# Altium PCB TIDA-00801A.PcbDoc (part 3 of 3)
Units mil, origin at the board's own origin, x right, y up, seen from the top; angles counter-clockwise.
Board outline 5000 x 3000 mil, 6 copper layers (Top Layer, Signal Layer 1, Signal Layer 2, Signal Layer 3, Signal Layer 4, Bottom Layer), stack 60.502 mil thick; 195 components, 95 nets, 602 pads, 757 vias.
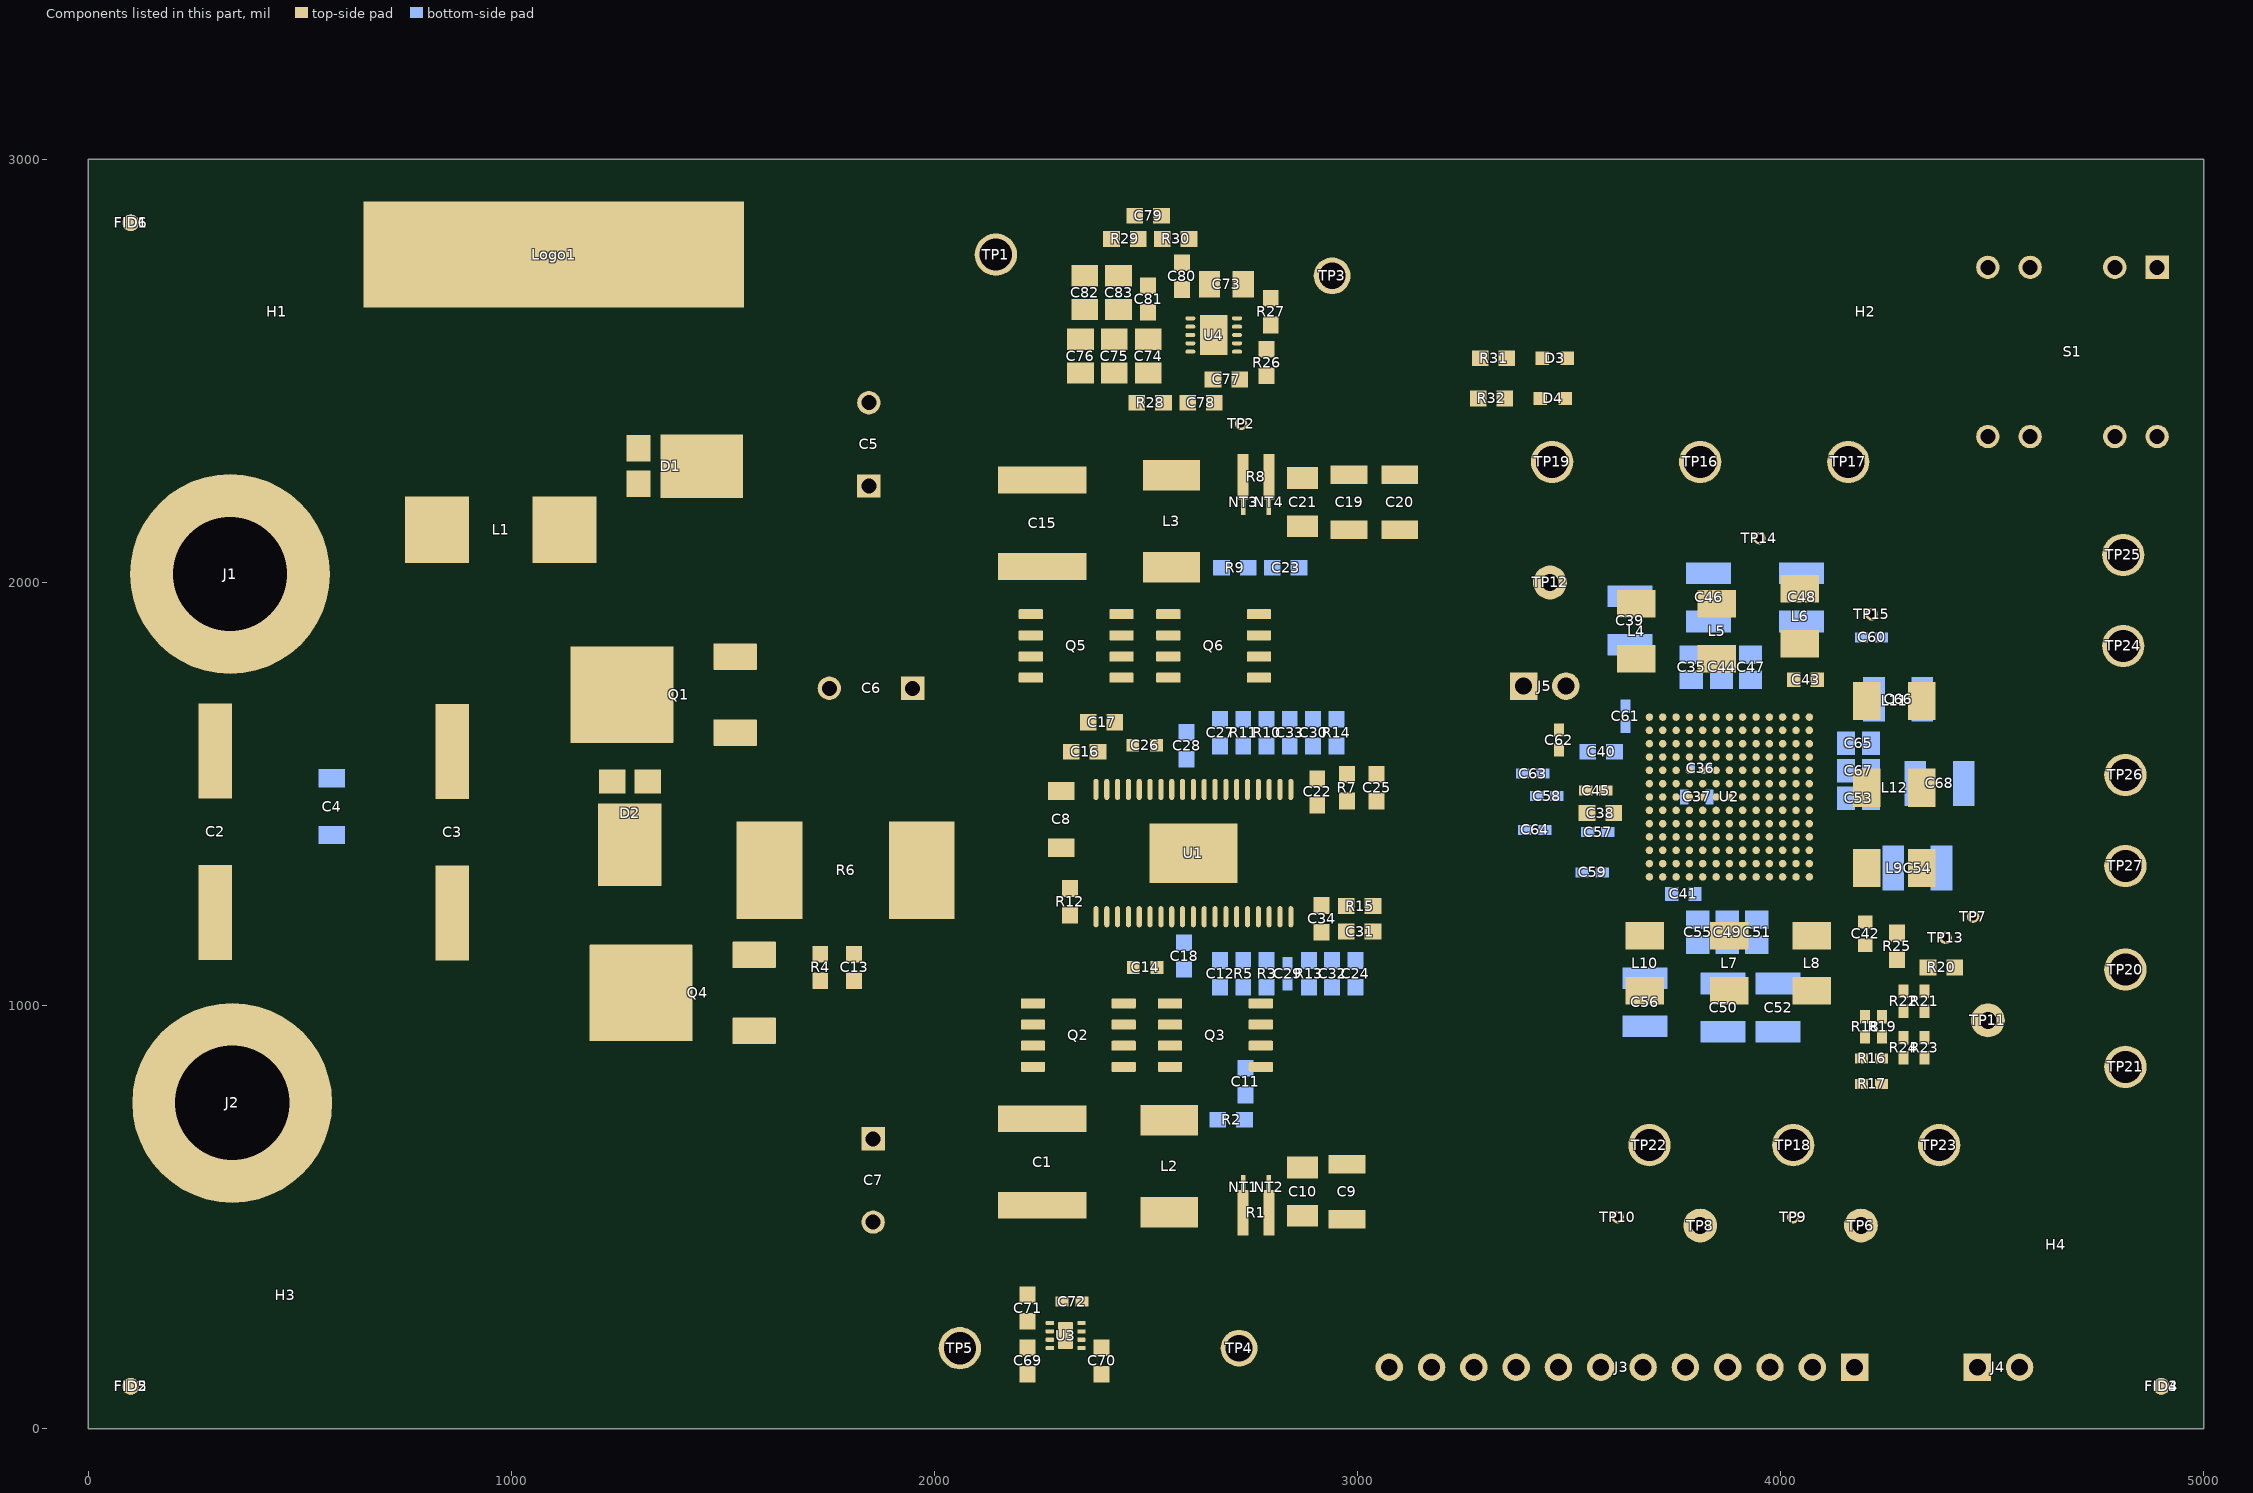
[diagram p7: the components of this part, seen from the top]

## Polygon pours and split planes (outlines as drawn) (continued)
NetL10_1 on Top Layer "TOP-SMPS7_SW" (solid, pour order 214): 3765.43,1308.21 3765.43,1331.31 3765.59,1331.85 3765.86,1332.95 3766.04,1334.08 3766.11,1335.22 3766.09,1336.36 3765.96,1337.5 3765.74,1338.62 3765.59,1339.17 3765.43,1339.71 3765.43,1362.81 3765.59,1363.35 3765.86,1364.45 3766.04,1365.58 3766.11,1366.72 3766.09,1367.86 3765.96,1369 3765.74,1370.12 3765.59,1370.67 3765.43,1371.21 3765.43,1377.83 3800.43,1377.83 3800.43,1149.83 3780.61,1130 3635.43,1130 3635.43,1157.83 3635.43,1199.88 3665.12,1199.88 3765.43,1299.81 3765.59,1300.35 3765.86,1301.45 3766.04,1302.58 3766.11,1303.72 3766.09,1304.86 3765.96,1306 3765.74,1307.12 3765.59,1307.67
NetL9_1 on Top Layer "TOP-SMPS6_SW" (solid, pour order 210): 4025.43,1447.83 4150.43,1447.83 4240.43,1357.83 4240.43,1287.83 4235.43,1282.83 4170.43,1282.83 4075.43,1417.83 4025.43,1417.83 4025.43,1447.83
NetL8_1 on Top Layer "TOP-SMPS5_SW" (solid, pour order 213): 3989.43,1231.94 4025.43,1197.83 4120.43,1197.83 4120.43,1132.83 4005.04,1132.83 4003.97,1133.67 4003,1134.37 4001.96,1134.98 4000.88,1135.51 3999.75,1135.93 3998.59,1136.26 3997.41,1136.48 3996.21,1136.6 3995.01,1136.62 3993.81,1136.53 3992.62,1136.34 3991.45,1136.04 3990.32,1135.64 3989.22,1135.15 3988.17,1134.56 3987.17,1133.88 3986.89,1133.67 3985.82,1132.83 3955.43,1132.83 3940.43,1147.83 3940.43,1205.05 3900.43,1262.83 3900.43,1377.83 3928.43,1377.83 3928.43,1298.83 3939.43,1287.83 3965.43,1287.83 3989.43,1263.83 3989.43,1231.94
NetL7_1 on Top Layer "TOP-SMPS4_SW" (solid, remove dead copper, pour order 207): 3920.43,1132.83 3820.43,1132.83 3820.43,1272.83 3829.72,1282.12 3856.25,1282.12 3865.43,1292.83 3865.43,1377.83 3890.43,1377.83 3890.43,1257.83 3920.43,1212.83 3920.43,1132.83
NetL6_1 on Top Layer "TOP-SMPS3_SW" (solid, pour order 211): 3915.43,1847.83 3965,1890 4090.43,1890 4090.43,1820.33 4005,1820.33 3963.17,1776.98 3962.22,1775.77 3961.57,1774.76 3961.01,1773.69 3960.6,1772.73 3960.27,1771.75 3959.98,1770.58 3959.79,1769.39 3959.71,1768.19 3959.73,1766.98 3959.85,1765.79 3960.08,1764.61 3960.27,1763.91 3960.43,1763.36 3960.43,1682.42 3960.43,1681.52 3960.43,1650.92 3960.43,1650.02 3960.43,1619.42 3960.43,1618.52 3960.43,1612.83 3955.43,1607.83 3930.43,1607.83 3930.43,1692.83 3915.43,1707.83
NetL5_1 on Top Layer "TOP-SMPS2_SW" (solid, pour order 208): 3835.43,1607.83 3835.43,1722.83 3800.43,1757.83 3800.43,1852.83 3900.43,1852.83 3900.43,1722.83 3865.43,1692.83 3865.43,1607.83 3835.43,1607.83
NetL4_1 on Top Layer "TOP-SMPS1_SW" (solid, pour order 209): 3786.65,1694.92 3694.11,1782.83 3600.43,1782.83 3600.43,1852.83 3695.43,1852.83 3825.43,1722.83 3825.43,1607.83 3800.43,1607.83 3800.43,1681.83 3797.34,1684.77 3797.04,1685.76 3796.66,1686.83 3796.19,1687.87 3795.64,1688.87 3794.99,1689.81 3794.27,1690.69 3793.47,1691.51 3792.6,1692.25 3791.68,1692.92 3790.7,1693.5 3789.67,1693.99 3788.6,1694.39 3787.66,1694.67 3786.65,1694.92
3V3 on Top Layer "TOP-V_LDOUSB_IN2 2" (solid, pour order 201): 4002.96,1795.24 4020.43,1810 4055,1810 4055,1760 4020.43,1727.83 4020.43,1647.83 4015.43,1642.83 3995.43,1642.83 3987.28,1650.98 3987.28,1767.17 3987.29,1768.37 3987.28,1779.67 3998.69,1791.09 4000,1792.01 4000.91,1792.8 4001.75,1793.66 4002.51,1794.59
3V3 on Top Layer "TOP-V_LDOUSB_IN2 1" (solid, pour order 203): 4026.43,1395.83 4026.43,1407.83 4070.43,1407.83 4080.43,1397.83 4080.43,1389.5 4188.85,1217.83 4230.43,1217.83 4230.43,1187.83 4160.43,1187.83 4085.43,1292.83 4085.43,1337.83 4070.43,1352.83 4065.43,1352.83 4050.43,1367.83 4050.43,1371.83 4026.43,1395.83
5V0 on Top Layer "TOP-V_LDOUSB_IN2" (solid, pour order 198): 3692.82,1575.22 3700.43,1550 3660,1550 3625.43,1582.83 3625.43,1627.83 3645.43,1627.83 3685.43,1597.83 3700.43,1597.83 3700.43,1584.22 3698.58,1583.06 3697.64,1582.41 3696.76,1581.68 3695.95,1580.88 3695.21,1580.01 3694.55,1579.08 3693.97,1578.1 3693.48,1577.07 3693.12,1576.11
LDOVRTC on Top Layer "TOP-LDORTC" (solid, pour order 193): 3457.5,1619.96 3457.5,1569.96 3492.5,1569.96 3492.5,1619.96 3457.5,1619.96
3V3 on Top Layer "TOP-VSYS 6" (solid, pour order 194): 4076.43,1515.83 4027.43,1515.83 4027.43,1564.83 4076.43,1564.83 4076.43,1515.83
3V3 on Top Layer "TOP-VSYS 5" (solid, pour order 200): 3920.43,1607.83 3870.43,1607.83 3870.43,1687.83 3875.43,1692.83 3920.43,1692.83 3920.43,1607.83
3V3 on Top Layer "TOP-VSYS 4" (solid, pour order 199): 3856.43,1294.83 3806.43,1294.83 3806.43,1377.83 3856.43,1377.83 3856.43,1294.83
3V3 on Top Layer "TOP-VSYS 3" (solid, pour order 189): 4027.43,1452.83 4027.43,1469.83 4076.43,1469.83 4076.43,1452.83 4027.43,1452.83
3V3 on Top Layer "TOP-VSYS 2" (solid, pour order 190): 3784.84,1690.83 3793.43,1682.67 3793.43,1614.83 3788.43,1609.83 3780.43,1609.83 3775.43,1614.83 3775.43,1684.83 3780.43,1690.83 3784.84,1690.83
3V3 on Top Layer "TOP-VSYS 1" (solid, pour order 191): 3950.43,1300.83 3946.43,1295.83 3938.43,1295.83 3932.65,1300.65 3932.65,1375.83 3950.43,1375.83 3950.43,1300.83
5V0 on Top Layer "TOP-LDO12_IN 1" (solid, pour order 197): 3700.43,1447.83 3660.43,1447.83 3630.43,1432.83 3590.43,1432.83 3590.43,1477.83 3690.43,1477.83 3694.15,1472.26 3694.3,1471.84 3694.75,1470.79 3695.3,1469.78 3695.92,1468.83 3696.63,1467.94 3697.42,1467.11 3697.54,1466.99 3697.86,1466.69 3700.43,1462.83 3700.43,1447.83
SMPS7 on Top Layer "TOP-N46924472" (solid, pour order 204): 3620.43,922.83 3620.43,972.83 3635.43,992.83 3635.43,1042.83 3720.43,1042.83 3720.43,992.83 3740.43,972.83 3740.43,922.83 3620.43,922.83
SMPS3 on Top Layer "TOP-N46921072" (solid, pour order 206): 4000,1950 4000,2020 3985,2040 3985,2090 4105,2090 4105,2040 4090,2020 4090,1950 4000,1950
SMPS3 on Top Layer "Top Layer-No Net" (solid, remove dead copper, pour order 195): 2510,2655 2560,2655 2595,2620 2600,2615 2610,2615 2615,2610 2615,2600 2590,2600 2575,2600 2570,2605 2555,2620 2510,2620
VTT on Top Layer "Top Layer-No Net" (solid, remove dead copper, pour order 196): 2510,2600 2560,2600 2565,2595 2570,2590 2585,2590 2615,2590 2615,2575 2595,2575 2580,2575 2570,2575 2545,2550 2510,2550
VIN on Top Layer "Top Layer-No Net" (solid, remove dead copper, pour order 215): 1420,2355 1905,2355 2095,2355 2095,2165 2260,2165 2360,2165 2360,1990 2335,1965 2335,1860 2335,1770 2265,1700 2247.5,1682.5 2247.5,1082.5 2295,1035 2360,970 2360,910 2360,645 2135,645 1800,645 1800,715 2065,980 2065,1435 1790,1710 1790,1790 1420,1790
NetC45_1 on Signal Layer 2 "LY6-VBG_TPS" (solid, pour order 218): 3725.46,1498.91 3725.42,1487.84 3713.1,1487.84 3712.28,1488.24 3711.24,1488.7 3710.15,1489.06 3709.05,1489.33 3707.92,1489.5 3706.78,1489.57 3705.64,1489.55 3704.5,1489.42 3703.39,1489.19 3702.29,1488.87 3701.23,1488.46 3700.76,1488.24 3699.94,1487.84 3686.19,1487.84 3685.5,1487.87 3684.82,1487.96 3684.15,1488.1 3683.5,1488.31 3682.86,1488.57 3682.25,1488.89 3681.68,1489.26 3681.13,1489.68 3680.62,1490.14 3680.16,1490.65 3679.74,1491.19 3679.37,1491.77 3679.06,1492.38 3678.79,1493.01 3678.59,1493.67 3678.44,1494.34 3678.39,1494.69 3678.19,1495.81 3677.9,1496.91 3677.51,1497.99 3677.03,1499.02 3676.46,1500.01 3675.81,1500.94 3675.07,1501.82 3674.27,1502.63 3673.4,1503.36 3672.46,1504.02 3671.47,1504.59 3670.44,1505.07 3669.37,1505.47 3668.27,1505.76 3667.14,1505.96 3666.01,1506.06 3664.87,1506.06 3663.73,1505.97 3662.61,1505.77 3661.5,1505.48 3660.43,1505.09 3659.4,1504.61 3658.41,1504.04 3657.47,1503.38 3656.6,1502.65 3655.79,1501.85 3655.05,1500.97 3654.4,1500.04 3653.83,1499.05 3653.34,1498.02 3652.95,1496.95 3652.65,1495.84 3652.45,1494.72 3652.45,1494.69 3652.33,1494.01 3652.16,1493.35 3651.92,1492.7 3651.63,1492.08 3651.29,1491.48 3650.9,1490.92 3650.46,1490.39 3649.97,1489.91 3649.45,1489.47 3648.88,1489.07 3648.29,1488.73 3647.67,1488.44 3647.02,1488.2 3646.36,1488.02 3645.68,1487.9 3645,1487.84 3644.65,1487.84 3595.42,1487.84 3583.72,1496.94 3583.72,1528.43 3587.66,1532.37 3627.71,1532.37 3628.56,1531.93 3628.56,1531.92 3629.65,1531.42 3630.78,1531.01 3631.95,1530.7 3633.13,1530.49 3634.33,1530.39 3635.54,1530.39 3636.73,1530.5 3637.92,1530.71 3639.08,1531.02 3640.21,1531.44 3641.26,1531.93 3642.11,1532.37 3642.78,1532.37 3646.72,1536.31 3717.58,1536.31 3725.46,1528.43 3725.46,1513.18 3725.34,1512.71 3725.11,1511.59 3724.97,1510.46 3724.94,1509.31 3725.01,1508.18 3725.17,1507.05 3725.34,1506.29 3725.46,1505.82 3725.46,1498.91
5V0 on Signal Layer 2 "Top Layer-No Net" (solid, remove dead copper, pour order 219): 3620,1650 3475,1650 3471,1650 3436,1615 3431,1610 3390,1610 3170,1610 3120,1560 3115,1555 3115,1500 3115,665 3037.5,587.5 3015,565 2920,470 2865,415 2865,385 3050,255 3390,595 3505,710 3505,1215 3650,1360 3650,1395 3650,1620
3V3 on Signal Layer 3 "Top Layer-No Net" (solid, remove dead copper, pour order 221): 2897.17,2850 4347.17,2850 4672.17,2850 4672.17,225 3522.17,225 3022.17,225 2972.17,175 2847.17,50 2472.17,50 2472.17,460 2937.17,925 2937.17,965 2937.17,2485 2697.17,2725 2697.17,2850
VIN on Signal Layer 3 "Top Layer-No Net" (solid, remove dead copper, pour order 220): 1420,2355 1890,2355 2095,2150 2175,2150 2225,2100 2275,2050 2275,1975 2275,1825 2275,1725 2247.5,1697.5 2247.5,1082.5 2295,1035 2325,1005 2325,925 2325,850 2125,650 1800,650 1800,715 2065,980 2065,1435 1900,1600 1420,1600 1420,1695
GND on Signal Layer 3 "Top Layer-No Net" (solid, remove dead copper, pour order 222): 50,2850 2680,2850 2680,2670 2875,2475 2900,2450 2900,2400 2900,905 2425,430 2425,50 50,50
GND on Signal Layer 1 "Top Layer-No Net" (solid, remove dead copper, pour order 217): 50,2950 4950,2950 4950,50 50,50
GND on Signal Layer 4 "Top Layer-No Net" (solid, remove dead copper, pour order 223): 50,2950 4950,2950 4950,50 50,50

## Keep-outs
Keep-Out Layer:
  lines w10: -5,0 ccw(c0,0) 0,-5 ; -5,0 ccw(c0,0) 0,-5 ; -5,0 -5,3000 ; -5,3000 cw(c0,3000) 0,3005 ; -5,3000 cw(c0,3000) 0,3005 ; 0,-5 5000,-5 ; 0,3005 5000,3005 ; 5000,-5 ccw(c5000,0) 5005,0 ; 5000,-5 ccw(c5000,0) 5005,0 ; 5000,3005 cw(c5000,3000) 5005,3000 ; 5000,3005 cw(c5000,3000) 5005,3000 ; 5005,0 5005,3000
  text ".Layer_Name" at 577,-858.49 h60

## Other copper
Top Layer:
  rectangle net SMPS3: 2275,2620 2330,2670
  region net NetQ4_3: 1690,1440 1460,1440 1460,1030 1690,1030
  rectangle net SMPS9: 4361.56,1535 4870,1630
  region net GND: 3455,1688.62 3455,1643.62 3495,1643.62 3495,1688.62
  region net SMPS9: 4870,1460 4870,1582 4296,1582 4296,1460
  region net SMPS4_5: 3927,781 3927,1069 3811,1069 3811,781
  region net SMPS4_5: 4125,784 4125,1066 4019,1066 4019,784
  region net SMPS4_5: 4125,615 4125,992 3812,992 3812,615
  region net SMPS1_2: 3894,1927 3894,2345 3585,2345 3585,1927
  region net SMPS3: 4215,2072.83 4215,2345 3985,2345 3985,2072.83
  region net SMPS7: 3740,615 3740,930 3620,930 3620,615
  rectangle net VBAT: 55,1485 910,2350
  rectangle net NetD1_1: 955,1495 1405,2150
  rectangle net NetD2_3: 1070,910 1440,1480
  rectangle net PHB: 2410,1760 2605,1895
  rectangle net PHB: 2485,1760 2655,2075
  rectangle net PHA: 2415,690 2645,970
  rectangle net PHA: 2514,950 2645,1020
  rectangle net NetL3_2: 2490,2195 2740,2305
  rectangle net NetL2_2: 2485,455 2745,565
  rectangle net 5V0: 2780,435 3055,565
  rectangle net 3V3: 2777.72,2195 3175,2316.93
  rectangle net GND: 2830,2060 3150,2160
  rectangle net GND: 2830,590 3050,690
  rectangle net GND: 2139.3,490 2395,590
  rectangle net GND: 2110,2175 2380,2355
  rectangle net VIN: 2190,1490 2380,1530
  rectangle net GND: 2720,840 2850,970
  rectangle net GND: 2814,960 2850,990
  rectangle net GND: 2715,1725 2845,1895
  rectangle net 3V3: 2705,2620 2755,2710
  rectangle net 3V3: 2700,2700 2805,2785
  rectangle net 3V3: 4160,1180 4240,1225
  rectangle net GND: 4180,1115 4240,1160
  rectangle net 5V0: 2340,245 2395,365
  rectangle net 3V3: 2345,170 2415,215
  rectangle net 3V3: 2410,170 2600,210
  rectangle net 3V3: 2435,115 2600,175
  rectangle net 3V3_SW: 2120,170 2275,215
  rectangle net 3V3_SW: 2060,145 2180,235
  rectangle net NetD1_1: 960,2100 1335,2355
  pour cut-out: 3665,1775 3665,1650 3705,1610 3705,1440 3680,1415 3670,1415 3655,1400 3655,1310 3681.48,1283.52 3742.97,1283.52 3742.97,1302.97 3760,1320 3760,1380 3955,1380 3955,1295 3990,1295 4005,1280 4080,1280 4080,1334.49 4020,1394.49 4020,1605 4046,1631 4080,1631 4080,1635 4095,1650 4095,1705 4025,1705 4025,1635 4008.98,1618.98 3968.98,1618.98 3950,1600 3765,1600 3765,1625 3763.99,1626.01 3763.99,1706.01 3695,1775
  region net SMPS6: 4300,1385 4630,1385 4870,1145 4870,1030 4715,1030 4473.15,1271.85 4300,1271.85
  region net SMPS8: 4300,1785 4500,1785 4640,1925 4870,1925 4870,1665 4300,1665
  pour cut-out: 1440,1025 1670,1025 1670,900 1510,900 1440,900
  text ".CopyrightYear" at 542,70 h60
  text "TI" at 818,70 h60
  text "©" at 425,66.48 h105
  text ".Layer_Name" at 577,-858.49 h60
Signal Layer 1:
  pour cut-out: 3738.18,1899.94 ccw(c3753.23,1899.94) 3753.23,1884.88 ccw(c3753.23,1899.94) 3768.29,1899.94 ccw(c3753.23,1899.94) 3753.23,1914.99 ccw(c3753.23,1899.94)
  pour cut-out: 3958.88,1616.77 ccw(c3973.94,1616.77) 3973.94,1601.71 ccw(c3973.94,1616.77) 3988.99,1616.77 ccw(c3973.94,1616.77) 3973.94,1631.82 ccw(c3973.94,1616.77)
  pour cut-out: 3738.18,1649.94 ccw(c3753.23,1649.94) 3753.23,1634.88 ccw(c3753.23,1649.94) 3768.29,1649.94 ccw(c3753.23,1649.94) 3753.23,1664.99 ccw(c3753.23,1649.94)
  pour cut-out: 3958.88,1366.77 ccw(c3973.94,1366.77) 3973.94,1351.71 ccw(c3973.94,1366.77) 3988.99,1366.77 ccw(c3973.94,1366.77) 3973.94,1381.82 ccw(c3973.94,1366.77)
  pour cut-out: 3958.88,1366.77 ccw(c3973.94,1366.77) 3973.94,1351.71 ccw(c3973.94,1366.77) 3988.99,1366.77 ccw(c3973.94,1366.77) 3973.94,1381.82 ccw(c3973.94,1366.77)
  text ".Layer_Name" at 577,-858.49 h60
Signal Layer 2:
  rectangle net 5V0: 2335,255 3050,415
  region net 5V0: 3065,270 2930,135 2675,135 2540,270
  text ".Layer_Name" at 577,-858.49 h60
Signal Layer 3:
  pour cut-out: 3674.36,1868.76 ccw(c3689.42,1868.76) 3689.42,1853.7 ccw(c3689.42,1868.76) 3704.47,1868.76 ccw(c3689.42,1868.76) 3689.42,1883.81 ccw(c3689.42,1868.76)
  text ".Layer_Name" at 577,-858.49 h60
Signal Layer 4:
  rectangle net SMPS3: 2274,2621 2330,2685
  pour cut-out: 3706.01,1618.23 ccw(c3721.06,1618.23) 3721.06,1603.18 ccw(c3721.06,1618.23) 3736.12,1618.23 ccw(c3721.06,1618.23) 3721.06,1633.29 ccw(c3721.06,1618.23)
  pour cut-out: 3958.88,1366.77 ccw(c3973.94,1366.77) 3973.94,1351.71 ccw(c3973.94,1366.77) 3988.99,1366.77 ccw(c3973.94,1366.77) 3973.94,1381.82 ccw(c3973.94,1366.77)
  text ".Layer_Name" at 577,-858.49 h60
Bottom Layer:
  rectangle net SMPS3: 2274,2621 2321,2666
  rectangle net 3V3: 4110.43,1620 4145,1640
  rectangle net VBAT: 70,1510 850,2320
  rectangle net GND: 4235,1850 4320,1910
  region net SMPS1_2: 3741,1942 3741,2345 3562,2345 3562,1942
  region net SMPS1_2: 3894,1993 3894,2345 3729,2345 3729,1993
  region net SMPS3: 4215,2100 4215,2345 3985,2345 3985,2100
  region net SMPS7: 3740.72,615 3740.72,975 3620,975 3620,615
  rectangle net SMPS4_5: 3810,615 4125,965
  rectangle net SMPS9: 4395,1460 4870,1630
  rectangle net LDO3: 3964.87,1626.33 3985,1645
  rectangle net GND: 3505,1581 3564,1619
  rectangle net GND: 3384,1483 3415,1507
  pour cut-out: 3973.76,1753.96 3977.56,1750.16 3972.15,1744.75 3972.16,1744.74 3971.91,1744.51 3971.63,1744.3 3971.34,1744.11 3971.04,1743.95 3970.72,1743.82 3970.39,1743.72 3970.06,1743.65 3969.72,1743.6 3969.37,1743.59 3969.03,1743.6 3968.69,1743.65 3968.35,1743.72 3968.03,1743.82 3967.71,1743.95 3967.4,1744.11 3967.11,1744.3 3966.84,1744.51 3966.59,1744.74 3966.36,1744.99 3966.15,1745.27 3965.96,1745.56 3965.8,1745.86 3965.67,1746.18 3965.57,1746.51 3965.49,1746.84 3965.45,1747.14 3965.45,1754.52 3969.83,1754.52 3970.28,1754.41 3970.28,1754.4 3971.47,1754.18 3972.33,1754.08
  region net SMPS8: 4300,1785 4400,1785 4540,1925 4870,1925 4870,1665 4300,1665
  region net SMPS6: 4350,1385 4630,1385 4870,1145 4870,1030 4715,1030 4473.15,1271.85 4350,1271.85
  pour cut-out: 3738.18,1649.94 ccw(c3753.23,1649.94) 3753.23,1634.88 ccw(c3753.23,1649.94) 3768.29,1649.94 ccw(c3753.23,1649.94) 3753.23,1664.99 ccw(c3753.23,1649.94)
  pour cut-out: 3958.88,1366.77 ccw(c3973.94,1366.77) 3973.94,1351.71 ccw(c3973.94,1366.77) 3988.99,1366.77 ccw(c3973.94,1366.77) 3973.94,1381.82 ccw(c3973.94,1366.77)
  text ".Layer_Name" at 577,-858.49 h60

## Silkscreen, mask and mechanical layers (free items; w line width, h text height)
Top Overlay:
  text ".PCB_Rev" at 1344,2541 h110
  text ".tiD" at 805,2540 h110
  text "LDOVRTC" at 3535,2515 h75
  text "RESET_OUT" at 3535,2415 h75
  text "SYNC" at 3350,1820 h75
  text "VBAT" at 535,1805 h75
  text "GND" at 565,910 h75
  text "I2C_SDA" at 4460,210 h75 r45
  text "I2C_SCL" at 4560,210 h75 r45
  text "LDOUSB" at 3075,205 h75 r45
  text "LDOVRTC" at 3175,205 h75 r45
  text "GND" at 3275,205 h75 r45
  text "LDOVANA" at 3375,205 h75 r45
  text "LDO2" at 3475,205 h75 r45
  text "GND" at 3575,205 h75 r45
  text "LDO9" at 3675,205 h75 r45
  text "LDO1" at 3775,205 h75 r45
  text "GND" at 3875,205 h75 r45
  text "LDOLN" at 3975,205 h75 r45
  text "GND" at 4075,205 h75 r45
  text "LDO3" at 4175,205 h75 r45
  text ".Layer_Name" at 577,-858.49 h60
Bottom Overlay:
  text ".Layer_Name" at 577,-858.49 h60
Top Paste:
  text ".Layer_Name" at 577,-858.49 h60
Bottom Paste:
  text ".Layer_Name" at 577,-858.49 h60
Top Solder:
  text ".Layer_Name" at 577,-858.49 h60
  text ".Layer_Name" at 577,-858.49 h60
Bottom Solder:
  text ".Layer_Name" at 577,-858.49 h60
Drill Guide:
  text ".Layer_Name" at 577,-858.49 h60
M1 Board Outline:
  the board outline again, w10
  text ".Layer_Name" at 577,-858.49 h60
M2 Board Dimensions:
  rectangle: 125,-400 500,-275
  rectangle: 0,-275 125,-150
  lines w7: 0,-275 1000,-275 ; 125,-400 125,-150 ; 250,-400 250,-150 ; 500,-400 500,-150 ; 750,-400 750,-150 ; 0,-400 0,-150 1000,-150 1000,-400 0,-400
  text ".Layer_Name" at 577,-858.49 h60
M3 3D STEP Top:
  text ".Layer_Name" at 577,-858.49 h60
M4 3D STEP Bottom:
  text ".Layer_Name" at 577,-858.49 h60
M5 Assembly Top:
  lines w10: -292,-930.17 6308,-930.17 ; -292,-726.83 6310,-726.83 ; -292,-523.5 -292,-1133.5 3713,-1133.5 6310,-1133.5 6310,-523.5 -291.5,-523.5 -291.5,-1133.5 1284,-1133.5 ; 2173,-1133.5 2173,-523.5 ; 3440,-726.83 3440,-523.5 ; 4280,-726.83 4280,-523.5 ; 4902,-1140 4902,-937.17
  text "COMPONENTS MARKED 'DNP' SHOULD NOT BE POPULATED." at 1153.5,-318.5 h60
  text "ASSEMBLY VARIANT:" at 1153,-434 h60
  text ".VariantName" at 2189,-434 h60
  text "PCB VIEWED FROM TOP SIDE" at -228.5,-655.67 h60
  text "BOARD #:" at 2248,-655.67 h60
  text ".PRJ_Number" at 2793.5,-655.67 h60
  text "REV:" at 3638,-655.67 h60
  text ".PCB_Rev" at 3929.5,-655.67 h60
  text "SVN REV:" at 4476,-655.67 h60
  text ".VersionControl_RevNumber" at 4982,-655.67 h60
  text "PLOT NAME =" at -228.5,-1064.34 h60
  text ".plot_File_Name" at 577,-1064.34 h60
  text "GENERATED    :" at 2250,-1064.34 h60
  text ".Print_Date" at 3119.5,-1064.34 h60
  text ".Print_Time" at 3848.5,-1064.34 h60
  text "TEXAS INSTRUMENTS" at 5113,-1064.34 h60
M6 Assembly Bottom:
  lines w10: -292.5,-727.33 6309.5,-727.33 ; -290.5,-930.67 6309.5,-930.67 ; 1115.5,-1140.5 1115.5,-937.67 ; 1737.5,-727.33 1737.5,-524 ; 2577.5,-727.33 2577.5,-524 ; 3844.5,-1134 3844.5,-524 ; 4733.5,-1134 6309,-1134 6309,-524 -292.5,-524 -292.5,-1134 2304.5,-1134 6309.5,-1134 6309.5,-524
  text "COMPONENTS MARKED 'DNP' SHOULD NOT BE POPULATED." at 6102,-318 h60
  text ".VariantName" at 5058,-434 h60
  text "ASSEMBLY VARIANT:" at 6097,-434 h60
  text ".VersionControl_RevNumber" at 1035.5,-656.17 h60
  text "SVN REV:" at 1541.5,-656.17 h60
  text ".PCB_Rev" at 2088,-656.17 h60
  text "REV:" at 2379.5,-656.17 h60
  text ".PRJ_Number" at 3224,-656.17 h60
  text "BOARD #:" at 3769.5,-656.17 h60
  text "PCB VIEWED FROM BOTTOM SIDE" at 6246,-656.17 h60
  text "TEXAS INSTRUMENTS" at 904.5,-1064.84 h60
  text ".Print_Time" at 2169,-1064.84 h60
  text ".Print_Date" at 2898,-1064.84 h60
  text "GENERATED    :" at 3767.5,-1064.84 h60
  text ".plot_File_Name" at 5440.5,-1064.84 h60
  text "PLOT NAME =" at 6246,-1064.84 h60
M9 Title Sheet:
  drawing of 57 lines, arcs and shapes, not listed
  text "1" at 739.84,8036.5 h70
  text "2" at 3235.5,8036.5 h70
  text "3" at 5724.84,8036.5 h70
  text "4" at 8231.51,8036.5 h70
  text "5" at 10730.5,8036.5 h70
  text "6" at 13235.5,8036.5 h70
  text "A" at -416.5,6893.5 h70
  text "A" at 14383.5,6893.5 h70
  text "B" at -416.5,4513.5 h70
  text "B" at 14383.5,4513.5 h70
  text "C" at -416.5,2138.5 h70
  text "C" at 14383.5,2138.5 h70
  text "PROJECT TITLE:" at 11343.5,277.5 h45
  text ".PRJ_Title" at 11393.5,144.17 h70
  text "DESIGNED FOR:" at 11343.5,-23.5 h45
  text ".PRJ_Customer" at 11393.5,-163.5 h70
  text "D" at -416.5,-231.5 h70
  text "D" at 14383.5,-231.5 h70
  text "FILE NAME:" at 11343.5,-323.5 h45
  text ".PCB_File_Name_No_Path" at 11393.5,-443.5 h70
  text "Texas Instruments (TI) and/or its licensors do not warrant the accuracy or completeness of this specification" at 6374,-605.34 h45
  text "ENGINEER:" at 11343.5,-613.5 h45
  text "LAYOUT BY:" at 12848.5,-613.5 h45
  text "or any information contained therein. TI and/or its licensors do not warrant that this design will meet" at 6329.01,-718 h45
  text ".PRJ_Engineer" at 11393.5,-768.49 h70
  text ".PCB_Layout" at 12899,-768.49 h70
  text "the specifications, will be suitable for your application or fit for any particular purpose, or will operate in" at 6329.01,-830.67 h45
  text ".Layer_Name" at 577,-858.49 h60
  text "ALTIUM DESIGNER VERSION:" at 12848.5,-923.5 h45
  text "an implementation. TI and/or its licensors do not warrant that the design is production worthy. You should" at 6329.01,-943.33 h45
  text "completely validate and test your design implementation to confirm the system functionality for your application." at 6374,-1056 h45
  text ".print_Scale" at 11393.5,-1056.83 h70
  text ".Application_BuildNumber" at 12899,-1056.83 h70
  text "1" at 739.84,-1263.5 h70
  text "2" at 3235.5,-1263.5 h70
  text "3" at 5724.84,-1263.5 h70
  text "4" at 8231.51,-1263.5 h70
  text "5" at 10730.5,-1263.5 h70
  text "6" at 13235.5,-1263.5 h70
M10 Fab Notes:
  drawing of 185 lines, arcs and shapes, not listed
  text "DESIGN INFORMATION" at 12381.02,5910 h60
  text "MIN. TRACK WIDTH:" at 11736.46,5730 h60
  text "4" at 12832.7,5730 h60
  text "MIL" at 12987.46,5730 h60
  text "MIN. CLEARANCE:" at 11736.46,5598 h60
  text "4" at 12772.7,5598 h60
  text "MIL" at 12987.46,5598 h60
  text "MIN. VIA PAD SIZE:" at 11736.46,5466 h60
  text "17" at 12802.71,5466 h60
  text "MIL" at 12987.46,5466 h60
  text "0.05mm (2MIL)" at 12431.46,5324.29 h60
  text "MINIMUM ANNULAR RING" at 11407.23,5320 h60
  text "EXTERNAL" at 13139.46,5320 h60
  text "PER" at 11607.23,5202 h60
  text "IPC-D-275 CLASS 2 LEVEL C" at 11827.23,5202 h60
  text "MIL, HOLES" at 13315.46,5089.71 h60
  text "+/-" at 12923,5089 h60
  text "+/-" at 13777,5089 h60
  text "REGISTRATION TOLERANCES:" at 11407.23,5084 h60
  text "METAL" at 12607,5084 h60
  text "5" at 13183.2,5084 h60
  text "3" at 14016.2,5084 h60
  text "MIL" at 14132.46,5084 h60
  text "MATERIAL:" at 11332.46,4874.54 h60
  text "FR-4 High Tg" at 12318.9,4734.21 h60
  text "FR-408" at 11753.46,4725.64 h60
  text "X" at 12165.46,4725.64 h60
  text "OTHER" at 13241.46,4725.64 h60
  text "62 MIL (1.6mm) +/-10%" at 12073.56,4562.92 h60
  text "THICKNESS:" at 11407.23,4558.64 h60
  text "X" at 11945.4,4558.64 h60
  text "OTHER" at 13358.46,4558.64 h60
  text "TOLERANCE:" at 11407.23,4400.64 h60
  text "X" at 12246.53,4400.64 h60
  text "ANSI IPC-6012 TYPE 3 CLASS 2" at 12433.48,4400.64 h60
  text "OTHER +/-" at 12433.46,4244.64 h60
  text "BOW & TWIST:" at 11407.23,4087.64 h60
  text "X" at 12246.53,4087.64 h60
  text "ANSI IPC-6012 TYPE 3 CLASS 2" at 12433.48,4087.64 h60
  text "OTHER +/-" at 12433.46,3929.13 h60
  text "DRILLING:" at 11332.46,3790.64 h60
  text "REFERENCE:" at 11407.23,3673.64 h60
  text "X" at 12055.46,3673.64 h60
  text "AS SHOWN" at 12242.46,3673.64 h60
  text "X" at 12956.46,3673.64 h60
  text "NC_DRILL FILES" at 13093.46,3673.64 h60
  text "PTH MIN COPPER THICKNESS:" at 11407.23,3515.64 h60
  text "X" at 12757.46,3515.64 h60
  text "1MIL" at 12894.46,3515.64 h60
  text "OTHER" at 13391.46,3515.64 h60
  text "BOARD FINISH:" at 11332.46,3356.64 h60
  text "SILKSCREEN:" at 11487.68,3238.64 h60
  text "X" at 12436.46,3238.64 h60
  text "TOP" at 12562.46,3238.64 h60
  text "X" at 12946.46,3238.64 h60
  text "BOTTOM" at 13073.46,3238.64 h60
  text "SILKSCREEN COLOR:" at 11487.68,3071.64 h60
  text "X" at 12435.42,3071.64 h60
  text "WHITE" at 12562.46,3071.64 h60
  text "OTHER" at 13073.46,3071.64 h60
  text "SOLDER RESIST COLOR:" at 11487.68,2901.64 h60
  text "X" at 12055.42,2742.44 h60
  text "GREEN" at 12182.46,2742.44 h60
  text "BLUE" at 12773.46,2742.44 h60
  text "OTHER" at 13311.46,2742.44 h60
  text "IMMERSION GOLD (ENIG)" at 12393.46,2553.92 h60
  text "ENEPIG" at 13731,2550.64 h60
  text "SURFACE FINISH:" at 11332.46,2549.64 h60
  text "X" at 12206.51,2549.64 h60
  text "IMM. TIN/SILVER OR EQUIV" at 11662,2392.64 h60
  text "OTHER" at 13093.46,2392.64 h60
  text "ARRAY/PANEL:" at 11332.46,2213.64 h60
  text "CUT AND TRIM PER MECH LAYER 1" at 12393.46,2209.35 h60
  text "N.C. ROUTE" at 12393.46,2057.64 h60
  text "X" at 13072.46,2057.64 h60
  text "V. SCORE" at 13259.46,2057.64 h60
  text "CERTIFICATION:" at 11332.46,1920.64 h60
  text "MATERIALS AND WORKMANSHIP FOR ALL PCBS" at 12057.46,1920.64 h60
  text "TO MEET OR EXCEED THE REQUIREMENTS OF:" at 12057.46,1822.64 h60
  text "X" at 11683.96,1686.13 h60
  text "ANSI IPC-A-600F CLASS ->" at 11822.96,1686.13 h60
  text "X" at 13462.02,1686.13 h60
  text "2" at 13580.96,1686.14 h60
  text "1" at 13265.96,1684.64 h60
  text "3" at 13934.96,1684.64 h60
  text "X" at 11686.02,1526.64 h60
  text "UL 94V-0" at 11822.96,1526.64 h60
  text "X" at 12498.02,1526.64 h60
  text "RoHS" at 12634.96,1526.64 h60
  text "OTHER" at 13279.36,1526.64 h60
  text "PER ORDER" at 13676.42,1526.64 h60
  text "ADDITIONAL REQUIREMENTS:" at 11332.46,1385.64 h60
  text "MICROSECTION:" at 11407.23,1270.64 h60
  text "YES" at 12312.96,1270.64 h60
  text "REQUIRED" at 13174.46,1114.49 h60
  text "BARE BOARD ELEC. TEST:" at 11407.23,1111.64 h60
  text "NONE" at 12712.96,1111.64 h60
  text "X" at 13047.46,1111.64 h60
  text "PER ORDER" at 13766.46,1111.64 h60
  text "MANUFACTURER'S UL:" at 11407.23,954.64 h60
  text "RAIL" at 12572.96,950.35 h60
  text "METAL" at 13064.77,950.35 h60
  text "X" at 13440,950 h60
  text "SILK" at 13576.46,950.35 h60
  text "All 7.80MIL vias holes must be filled and plated closed" at 5292.23,311.64 h60
  text ".Layer_Name" at 577,-858.49 h60
M11 Gerber Information:
  lines w10: -292,-930.17 6308,-930.17 ; -292,-726.83 6310,-726.83 ; -292,-523.5 -292,-1133.5 3713,-1133.5 6310,-1133.5 6310,-523.5 -291.5,-523.5 -291.5,-1133.5 1284,-1133.5 ; 2173,-1133.5 2173,-523.5 ; 3440,-726.83 3440,-523.5 ; 4280,-726.83 4280,-523.5 ; 4902,-1140 4902,-937.17
  text "ALL ARTWORK VIEWED FROM TOP SIDE" at -228.5,-655.67 h60
  text "BOARD #:" at 2248,-655.67 h60
  text ".PRJ_Number" at 2793.5,-655.67 h60
  text "REV:" at 3638,-655.67 h60
  text ".PCB_Rev" at 3929.5,-655.67 h60
  text "SVN REV:" at 4476,-655.67 h60
  text ".VersionControl_RevNumber" at 4982,-655.67 h60
  text "LAYER NAME =" at -228.5,-858.49 h60
  text "PLOT NAME =" at -228.5,-1064.34 h60
  text ".plot_File_Name" at 577,-1064.34 h60
  text "GENERATED    :" at 2250,-1064.34 h60
  text ".Print_Date" at 3119.5,-1064.34 h60
  text ".Print_Time" at 3848.5,-1064.34 h60
  text "TEXAS INSTRUMENTS" at 5113,-1064.34 h60
M12 Stackup:
  drawing of 399 lines, arcs and shapes, not listed
  text "Layer" at 9785,7860 h60
  text "Name" at 10194.91,7860 h60
  text "Material" at 11134.65,7860 h60
  text "Thickness" at 11994.42,7860 h60
  text "Constant" at 12644.26,7860 h60
  text "Board Layer Stack" at 13214.12,7860 h60
  text "1" at 9785,7740 h60
  text "Top Overlay" at 10194.91,7740 h60
  text "2" at 9785,7620 h60
  text "Top Solder" at 10194.91,7620 h60
  text "Solder Resist" at 11134.65,7620 h60
  text "0.40mil" at 11994.42,7620 h60
  text "3.5" at 12644.26,7620 h60
  text "3" at 9785,7500 h60
  text "Top Layer" at 10194.91,7500 h60
  text "Copper" at 11134.65,7500 h60
  text "1.42mil" at 11994.42,7500 h60
  text "4" at 9785,7380 h60
  text "Dielectric1" at 10194.91,7380 h60
  text "FR-4 High TG" at 11134.65,7380 h60
  text "10.00mil" at 11994.42,7380 h60
  text "4.8" at 12644.26,7380 h60
  text "5" at 9785,7260 h60
  text "Signal Layer 1" at 10194.91,7260 h60
  text "Copper" at 11134.65,7260 h60
  text "1.42mil" at 11994.42,7260 h60
  text "6" at 9785,7140 h60
  text "Dielectric 2" at 10194.91,7140 h60
  text "FR-4 High TG" at 11134.65,7140 h60
  text "10.00mil" at 11994.42,7140 h60
  text "4.8" at 12644.26,7140 h60
  text "7" at 9785,7020 h60
  text "Signal Layer 2" at 10194.91,7020 h60
  text "Copper" at 11134.65,7020 h60
  text "1.42mil" at 11994.42,7020 h60
  text "8" at 9785,6900 h60
  text "Dielectric 3" at 10194.91,6900 h60
  text "FR-4 High TG" at 11134.65,6900 h60
  text "12.00mil" at 11994.42,6900 h60
  text "4.8" at 12644.26,6900 h60
  text "9" at 9785,6780 h60
  text "Signal Layer 3" at 10194.91,6780 h60
  text "Copper" at 11134.65,6780 h60
  text "1.42mil" at 11994.42,6780 h60
  text "10" at 9785,6660 h60
  text "Dielectric 4" at 10194.91,6660 h60
  text "FR-4 High TG" at 11134.65,6660 h60
  text "10.00mil" at 11994.42,6660 h60
  text "4.8" at 12644.26,6660 h60
  text "11" at 9785,6540 h60
  text "Signal Layer 4" at 10194.91,6540 h60
  text "Copper" at 11134.65,6540 h60
  text "1.42mil" at 11994.42,6540 h60
  text "12" at 9785,6420 h60
  text "Dielectric 5" at 10194.91,6420 h60
  text "FR-4 High TG" at 11134.65,6420 h60
  text "10.00mil" at 11994.42,6420 h60
  text "4.8" at 12644.26,6420 h60
  text "13" at 9785,6300 h60
  text "Bottom Layer" at 10194.91,6300 h60
  text "Copper" at 11134.65,6300 h60
  text "1.42mil" at 11994.42,6300 h60
  text "14" at 9785,6180 h60
  text "Bottom Solder" at 10194.91,6180 h60
  text "Solder Resist" at 11134.65,6180 h60
  text "0.40mil" at 11994.42,6180 h60
  text "3.5" at 12644.26,6180 h60
  text "15" at 9785,6060 h60
  text "Bottom Overlay" at 10194.91,6060 h60
  text ".Layer_Name" at 577,-858.49 h60
M13 Component Bodies Top:
  text ".Layer_Name" at 577,-858.49 h60
M14 Component Bodies Bottom:
  text ".Layer_Name" at 577,-858.49 h60
M15 Courtyards Top:
  text ".Layer_Name" at 577,-858.49 h60
M16 Courtyards Bottom:
  text ".Layer_Name" at 577,-858.49 h60
Drill Drawing:
  circle w10: c5368.12,1640 r25
  circle w10: c5368.12,1040 r15
  circle w10: c5368.12,1040 r25
  lines w10: 5343.12,715 5368.12,727.5 5393.12,715 5380.62,740 5393.12,765 5368.12,752.5 5343.12,765 5355.62,740 5343.12,715 ; 5343.12,915 5393.12,915 5368.12,865 5343.12,915 ; 5343.12,1165 5368.12,1177.5 5393.12,1165 5380.62,1190 5393.12,1215 5368.12,1202.5 5343.12,1215 5355.62,1190 5343.12,1165 ; 5343.12,1315 5343.12,1327.5 5355.62,1340 5343.12,1352.5 5343.12,1365 5355.62,1365 5368.12,1352.5 5380.62,1365 5393.12,1365 5393.12,1352.5 5380.62,1340 5393.12,1327.5 5393.12,1315 5380.62,1315 5368.12,1327.5 5355.62,1315 5343.12,1315 ; 5343.12,1477.5 5355.62,1477.5 5368.12,1465 5380.62,1477.5 5393.12,1477.5 5380.62,1490 5393.12,1502.5 5380.62,1502.5 5368.12,1515 5355.62,1502.5 5343.12,1502.5 5355.62,1490 5343.12,1477.5 ; 5343.12,1815 5393.12,1815 5368.12,1765 5343.12,1815 ; 5343.12,1940 5368.12,1915 5393.12,1940 5368.12,1965 5343.12,1940 ; 5343.12,2077.5 5355.62,2077.5 5355.62,2065 5380.62,2065 5380.62,2077.5 5393.12,2077.5 5393.12,2102.5 5380.62,2102.5 5380.62,2115 5355.62,2115 5355.62,2102.5 5343.12,2102.5 5343.12,2077.5 ; 5353.12,725 5368.12,732.5 5383.12,725 5375.62,740 5383.12,755 5368.12,747.5 5353.12,755 5360.62,740 5353.12,725 ; 5353.12,905 5383.12,905 5368.12,875 5353.12,905
  lines w15: 5275,670 9153.97,670 ; 5275,2170 9153.97,2170 ; 5825.88,520 5825.88,2320 ; 6523.69,520 6523.69,2320 ; 7869.29,520 7869.29,2320 ; 8375.17,520 8375.17,2320 ; 5275,520 9153.97,520 9153.97,2320 5275,2320 5275,520
  text "Symbol" at 5365,2215 h72
  text "Hit Count" at 5870.88,2215 h72
  text "Finished Hole Size" at 6568.69,2215 h72
  text "Plated" at 7914.29,2215 h72
  text "Hole Type" at 8420.17,2215 h72
  text "2" at 5870.88,2065 h60
  text "63.00mil (1.600mm)" at 6568.69,2065 h60
  text "PTH" at 7914.29,2065 h60
  text "Round" at 8420.17,2065 h60
  text "2" at 5870.88,1915 h60
  text "270.00mil (6.858mm)" at 6568.69,1915 h60
  text "PTH" at 7914.29,1915 h60
  text "Round" at 8420.17,1915 h60
  text "7" at 5870.88,1765 h60
  text "17.72mil (0.450mm)" at 6568.69,1765 h60
  text "PTH" at 7914.29,1765 h60
  text "Round" at 8420.17,1765 h60
  text "14" at 5870.88,1615 h60
  text "7.87mil (0.200mm)" at 6568.69,1615 h60
  text "PTH" at 7914.29,1615 h60
  text "Round" at 8420.17,1615 h60
  text "14" at 5870.88,1465 h60
  text "35.43mil (0.900mm)" at 6568.69,1465 h60
  text "PTH" at 7914.29,1465 h60
  text "Round" at 8420.17,1465 h60
  text "14" at 5870.88,1315 h60
  text "76.00mil (1.930mm)" at 6568.69,1315 h60
  text "PTH" at 7914.29,1315 h60
  text "Round" at 8420.17,1315 h60
  text "20" at 5870.88,1165 h60
  text "40.00mil (1.016mm)" at 6568.69,1165 h60
  text "PTH" at 7914.29,1165 h60
  text "Round" at 8420.17,1165 h60
  text "104" at 5870.88,1015 h60
  text "7.80mil (0.198mm)" at 6568.69,1015 h60
  text "PTH" at 7914.29,1015 h60
  text "Round" at 8420.17,1015 h60
  text "167" at 5870.88,865 h60
  text "8.00mil (0.203mm)" at 6568.69,865 h60
  text "PTH" at 7914.29,865 h60
  text "Round" at 8420.17,865 h60
  text "472" at 5870.88,715 h60
  text "10.00mil (0.254mm)" at 6568.69,715 h60
  text "PTH" at 7914.29,715 h60
  text "Round" at 8420.17,715 h60
  text "816 Total" at 5870.88,565 h60
  text "All 7.80MIL vias holes must be filled and plated closed" at 5292.23,306.64 h60
  text ".Layer_Name" at 577,-858.49 h60

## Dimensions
0,0 to 5000,0 on M2 Board Dimensions
0,0 to 0,3000 on M2 Board Dimensions
0,-400 to 1000,-400 on M2 Board Dimensions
